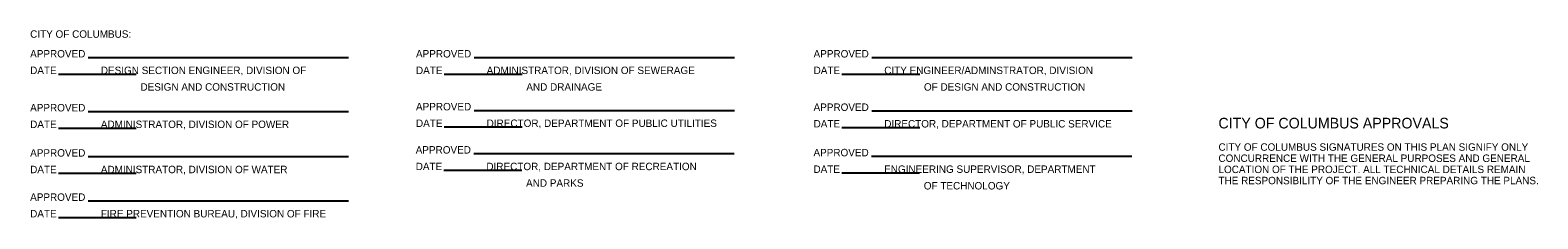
# Model space of a CAD drawing. Extents: x -42.2 to 34, y 0 to 22.
# Drawn here: x -42.21 to -13.81, y 6.47 to 10.02 of the extents above; entities that cross this region are included whole.
import ezdxf

# ---------------------------------------------------------------- set-up
doc = ezdxf.new("R2010")
doc.units = 0
doc.layers.add('SH_Data', color=7, linetype='Continuous')

msp = doc.modelspace()

# ---------------------------------------------------------------- linework, layer by layer
at = {"layer": 'SH_Data'}
for p, q in [((-41.121, 9.51), (-36.215, 9.51)), ((-33.852, 9.51), (-28.947, 9.51)), ((-26.362, 9.51), (-21.457, 9.51)), ((-41.682, 9.198), (-40.215, 9.198)), ((-34.414, 9.198), (-32.947, 9.198)), ((-26.924, 9.198), (-25.457, 9.198)), ((-41.121, 8.495), (-36.215, 8.495)), ((-33.852, 8.515), (-28.947, 8.515)), ((-26.362, 8.505), (-21.457, 8.505)), ((-41.682, 8.183), (-40.215, 8.183)), ((-34.414, 8.203), (-32.947, 8.203)), ((-26.924, 8.193), (-25.457, 8.193)), ((-33.858, 7.702), (-28.952, 7.702)), ((-41.121, 7.645), (-36.215, 7.645)), ((-34.419, 7.39), (-32.952, 7.39)), ((-26.365, 7.651), (-21.459, 7.651)), ((-41.682, 7.333), (-40.215, 7.333)), ((-26.926, 7.339), (-25.459, 7.339)), ((-41.121, 6.813), (-36.215, 6.813)), ((-41.682, 6.501), (-40.215, 6.501))]:
    msp.add_line(p, q, dxfattribs=at)

# ---------------------------------------------------------------- texts
for s, height, p in [('CITY OF COLUMBUS:', 0.14, (-42.215, 9.881)), ('APPROVED', 0.14, (-42.215, 9.51)), ('APPROVED', 0.14, (-34.947, 9.51)), ('APPROVED', 0.14, (-27.457, 9.51)), ('DATE                DESIGN SECTION ENGINEER, DIVISION OF ', 0.14, (-42.215, 9.198)), ('DATE                ADMINISTRATOR, DIVISION OF SEWERAGE ', 0.14, (-34.947, 9.198)), ('DATE                CITY ENGINEER/ADMINSTRATOR, DIVISION', 0.14, (-27.457, 9.198)), ('DESIGN AND CONSTRUCTION', 0.14, (-40.137, 8.886)), ('AND DRAINAGE', 0.14, (-32.868, 8.886)), ('OF DESIGN AND CONSTRUCTION', 0.14, (-25.378, 8.886)), ('APPROVED', 0.14, (-42.215, 8.495)), ('APPROVED', 0.14, (-34.947, 8.515)), ('APPROVED', 0.14, (-27.457, 8.505)), ('DATE                ADMINISTRATOR, DIVISION OF POWER', 0.14, (-42.215, 8.183)), ('DATE                DIRECTOR, DEPARTMENT OF PUBLIC UTILITIES', 0.14, (-34.947, 8.203)), ('DATE                DIRECTOR, DEPARTMENT OF PUBLIC SERVICE', 0.14, (-27.457, 8.193)), ('CITY OF COLUMBUS APPROVALS', 0.2, (-19.83, 8.175)), ('APPROVED', 0.14, (-42.215, 7.645)), ('APPROVED', 0.14, (-34.952, 7.702)), ('APPROVED', 0.14, (-27.459, 7.651)), ('CITY OF COLUMBUS SIGNATURES ON THIS PLAN SIGNIFY ONLY ', 0.14, (-19.83, 7.755)), ('CONCURRENCE WITH THE GENERAL PURPOSES AND GENERAL ', 0.14, (-19.83, 7.545)), ('DATE                ADMINISTRATOR, DIVISION OF WATER', 0.14, (-42.215, 7.333)), ('DATE                DIRECTOR, DEPARTMENT OF RECREATION ', 0.14, (-34.952, 7.39)), ('DATE                ENGINEERING SUPERVISOR, DEPARTMENT', 0.14, (-27.459, 7.339)), ('LOCATION OF THE PROJECT. ALL TECHNICAL DETAILS REMAIN', 0.14, (-19.83, 7.335)), ('AND PARKS', 0.14, (-32.873, 7.078)), ('OF TECHNOLOGY', 0.14, (-25.381, 7.027)), ('THE RESPONSIBILITY OF THE ENGINEER PREPARING THE PLANS.', 0.14, (-19.83, 7.125)), ('APPROVED', 0.14, (-42.215, 6.813)), ('DATE                FIRE PREVENTION BUREAU, DIVISION OF FIRE', 0.14, (-42.215, 6.501))]:
    msp.add_text(s, height=height, dxfattribs=at).set_placement(p)

doc.saveas('drawing.dxf')
